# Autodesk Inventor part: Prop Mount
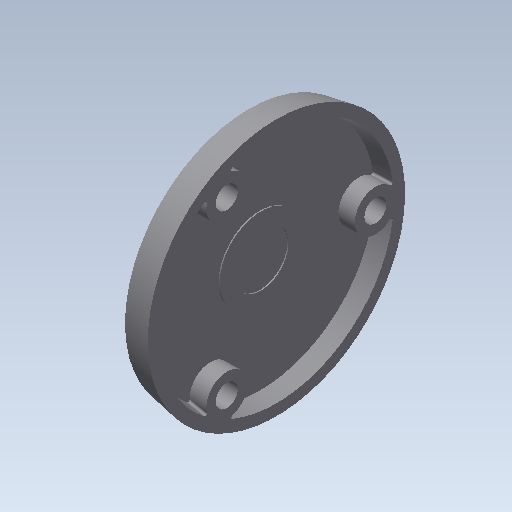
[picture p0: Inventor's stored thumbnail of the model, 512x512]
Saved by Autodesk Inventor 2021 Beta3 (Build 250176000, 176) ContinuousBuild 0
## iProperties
Created: 2013-05
Part Number: Prop Mount
Material: Generic
Document SubType Name: Modeling
Designer: John
Density: 1 g/cm^3
Appearance: Default
Author: John
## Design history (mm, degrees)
sketch "Sketch1"
  geometry: C1 r 28.575 at (0, 0); 1 further point
  constraints: 1 centre point, 1 coincident
  dimensions: "d2" = 57.15 diameter of C1
extrude "Extrusion1" new body sketch "Sketch1" distance "d0" = 6.35; taper "d1" = 10 deg
shell "Shell1" dims "d3" = 2.54
sketch "Sketch2"
  geometry: C1 r 26.444 at (0, 0) reference; C2 r 4.763 at (22.86, 0)
  constraints: 1 centre point
  dimensions: "d4" = 22.86 distance of C1.centre C2.centre; "d5" = 9.525 diameter of C2
extrude "Extrusion2" join sketch "Sketch2" stored distance "d6" = 25.4; taper "d7" = 0 deg
fillet "Fillet1" dims "d13" = 0.39687
pattern_circular "Circular Pattern1" dims angle "d15" = 360 deg
sketch "Sketch5"
  geometry: C1 r 9.525 at (-22.86, 0); C2 r 6.35 at (-22.86, 0); A1 r 23.451 centre (-22.86, 0) between (-38.422, 17.543) and (-38.422, -17.543); 5 further points
  constraints: 3 centre point, 3 coincident, 2 point on circle, 1 other
  dimensions: "d18" = 19.05 diameter of C1; "d19" = 3.175 radial gap between concentric circles of C1 C2
extrude "Extrusion4" join sketch "Sketch5" distance "d20" = 0.254; taper "d21" = 0 deg
sketch "Sketch6"
  geometry: A1 r 4.763 centre (-11.43, 19.797) between (-16.048, 20.963) and (-10.131, 24.379) reference; A2 r 4.763 centre (22.86, 0) between (26.178, 3.416) and (26.178, -3.416) reference; A3 r 4.763 centre (-11.43, -19.797) between (-10.131, -24.379) and (-16.048, -20.963) reference
hole "Hole1" sketch "Sketch6" at (-11.43, 19.797), (22.86, 0), (-11.43, -19.797) diameter "d22" = 5.1054; stored, may be unused: countersink angle "d26" = 82 deg, drill point angle "d28" = 118 deg; dims "d23" = 19.05, "d24" = 9.525, "d25" = 6.35, "d27" = 25.4
sketch "Sketch7"
  geometry: L1 (-0.127, 2.54)-(0.127, 2.54); L2 (0.127, 2.54)-(0.127, 12.7); L3 (0.127, 12.7)-(-0.127, 12.7); L4 (-0.127, 12.7)-(-0.127, 2.54); C1 r 28.575 at (0, 0) reference
  constraints: 8 end point, 2 parallel, 1 horizontal, 1 perpendicular
  dimensions: "d29" = 10.16 distance of L3.end L1.start; "d30" = 0.254 distance of L1.start L1.end; "d31" = 2.54 distance from line of C1.centre L1; "d32" = 0.127 distance from line of C1.centre L4 (= 0.5 x d30)
extrude "Extrusion5" join sketch "Sketch7" distance "d33" = 0.0254; taper "d34" = 0 deg
sketch "Sketch8"
  geometry: C1 r 2.553 at (-22.86, 0) reference; C2 r 1.587 at (-17.78, 0)
  constraints: 1 centre point
  dimensions: "d38" = 3.175 diameter of C2; "d39" = 5.08 distance of C2.centre C1.centre
extrude "Extrusion6" join sketch "Sketch8" distance "d40" = 3.175; taper "d41" = 0 deg
pattern_circular "Circular Pattern3" dims angle "d43" = 360 deg
body "Solid1"
pattern_circular "Circular Pattern2" dims angle "d36" = 360 deg
